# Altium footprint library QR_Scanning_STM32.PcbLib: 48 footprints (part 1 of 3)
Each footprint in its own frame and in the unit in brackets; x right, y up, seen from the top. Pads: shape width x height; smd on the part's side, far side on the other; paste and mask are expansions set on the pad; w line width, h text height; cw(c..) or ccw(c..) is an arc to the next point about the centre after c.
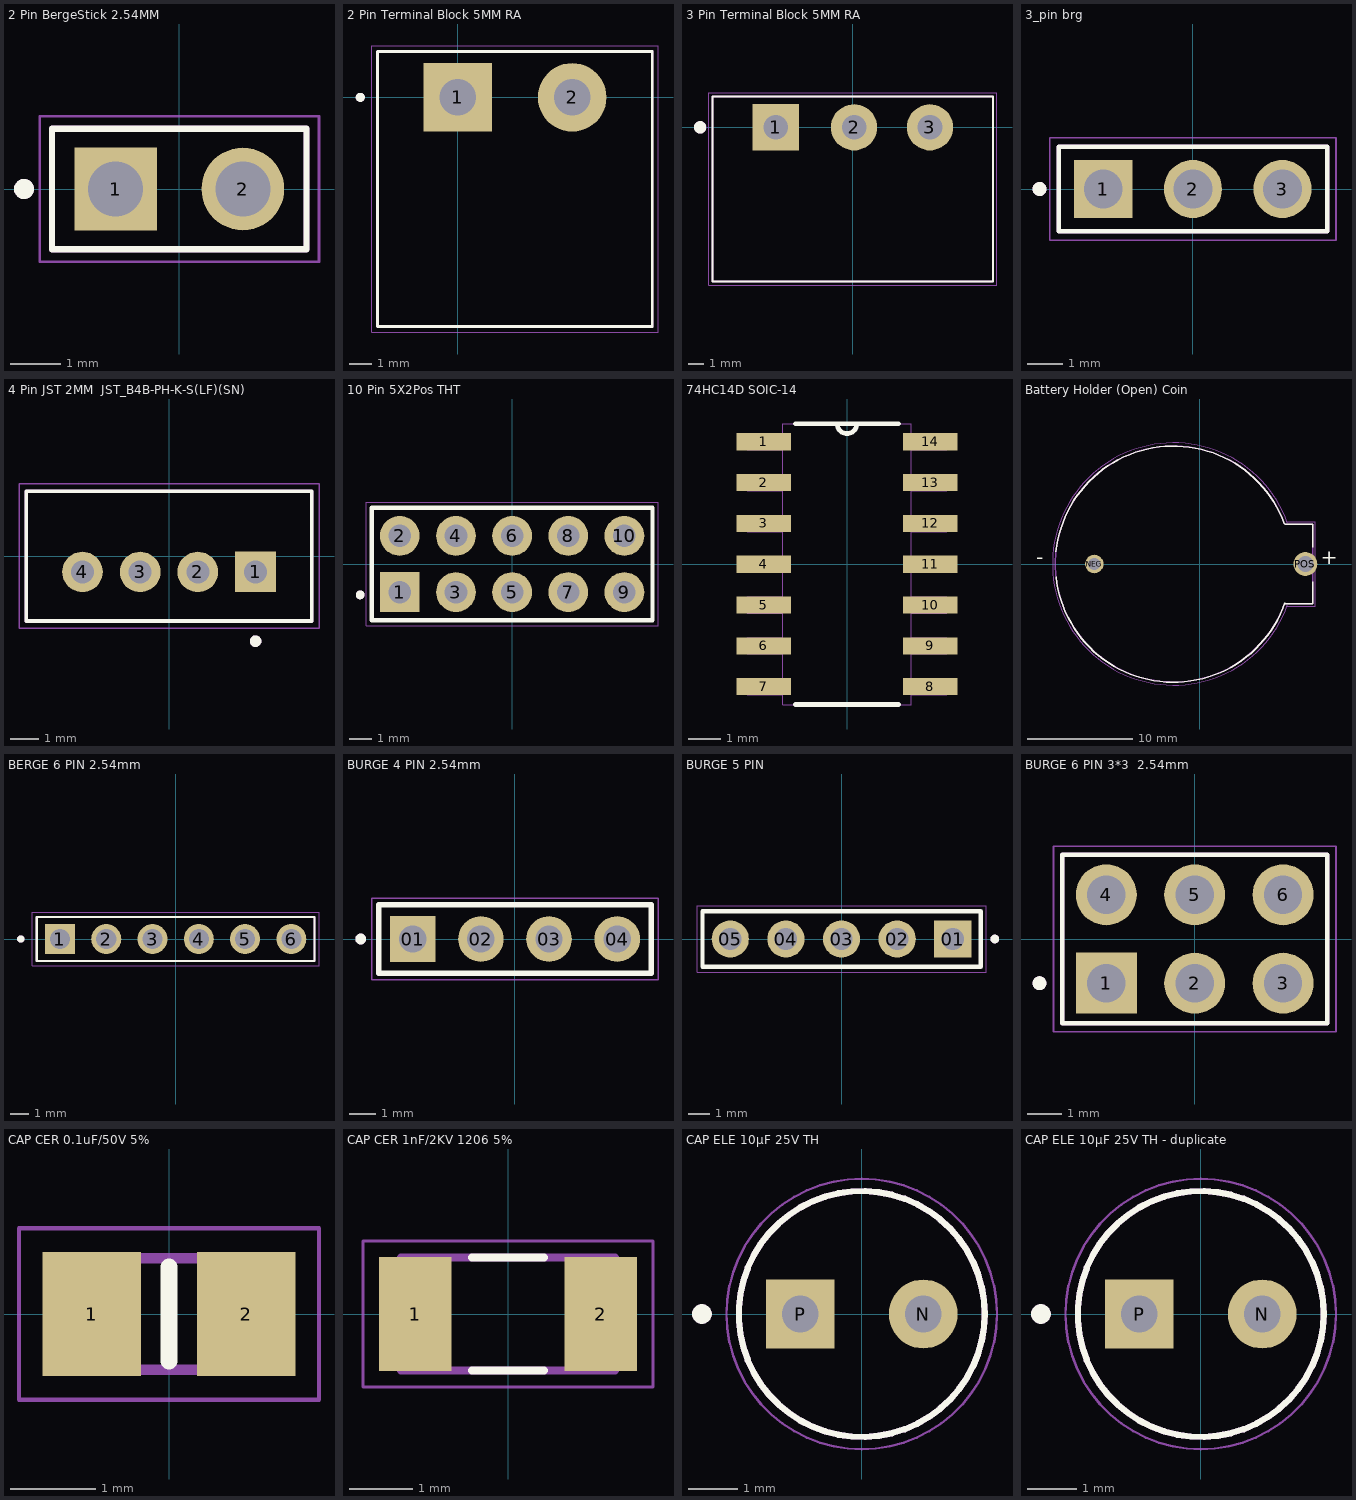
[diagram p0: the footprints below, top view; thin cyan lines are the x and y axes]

## 2 Pin BergeStick 2.54MM [mm] "2 Pin 2Pos THT BergeStick 2.54MM Amphenol 68000-402HLF 3A AMPHENOL_68000-402HLF"
height 10.8
pads (2):
  rect 1.65x1.65 hole 1.1: 1(-1.27,0)
  round 1.65 hole 1.1: 2(1.27,0)
Top Overlay:
  circle w0.2: c-3.1,0 r0.1
  lines w0.127: -2.54,-1.205 2.54,-1.205 2.54,1.205 -2.54,1.205 -2.54,-1.205
Mechanical 13:
  circle w0.2: c-3.1,0 r0.1
  lines w0.127: -2.54,-1.205 2.54,-1.205 2.54,1.205 -2.54,1.205 -2.54,-1.205
Mechanical 15:
  lines w0.05: -2.79,-1.455 2.79,-1.455 2.79,1.455 -2.79,1.455 -2.79,-1.455
3D body "step_temp.STEP": height 8.39, standoff -2.41, extent -2.54,-1.205 2.54,1.205

## 2 Pin Terminal Block 5MM RA [mm] "2 Pin Terminal Block HDR 5MM THT RA_OQ0271510000G"
height 8.5
pads (2):
  rect 3x3 hole 1.6: 1(0,0)
  round 3 hole 1.6: 2(5,0)
Top Overlay:
  circle w0.2: c-4.25,0 r0.1
  lines w0.127: -3.5,-10 -3.5,2 8.5,2 8.5,-10 -3.5,-10
Mechanical 13:
  circle w0.2: c-4.25,0 r0.1
  lines w0.127: -3.5,-10 -3.5,2 8.5,2 8.5,-10 -3.5,-10
Mechanical 15:
  lines w0.05: -3.75,-10.25 -3.75,2.25 8.75,2.25 8.75,-10.25 -3.75,-10.25
3D body "step_temp.STEP": height 8.5, standoff -3.5, extent -3.5,-10 8.5,2

## 3 Pin Terminal Block 5MM RA [mm] "3 Pin Terminal Block HDR 5MM THT RA 231-433_001-000"
pads (3):
  rect 3x3 hole 1.6: 1(-5,0)
  round 3 hole 1.6: 2(0.08,0) 3(5,0)
Top Overlay:
  circle w0.4: c-9.91,0 r0.2
  lines w0.127: -9.1,-10 9.1,-10 9.1,2 -9.1,2 -9.1,-10
Mechanical 13:
  circle w0.4: c-9.906,0 r0.2
  lines w0.127: -9.1,-10 -9.1,2 9.1,2 9.1,-10 -9.1,-10
Mechanical 15:
  lines w0.05: -9.35,-10.25 9.35,-10.25 9.35,2.25 -9.35,2.25 -9.35,-10.25
3D body "2342079-3--3DModel-STEP-1.STEP": height 8.97, standoff -2.28, extent -8.418,-10.064 8.382,1.936

## 3_pin brg [mm] "3_pin brg 2.54mm"
height 8.58
pads (3):
  rect 1.65x1.65 / inner round 1.65 / far side rect 1.65x1.65 hole 1.1: 1(-2.54,0)
  round 1.65 hole 1.1: 2(0,0) 3(2.54,0)
Top Overlay:
  circle w0.2: c-4.35,0 r0.1
  lines w0.127: -3.81,-1.205 -3.81,1.205 3.81,1.205 3.81,-1.205 -3.81,-1.205
Mechanical 13:
  circle w0.2: c-4.35,0 r0.1
  lines w0.127: -3.81,-1.205 -3.81,1.205 3.81,1.205 3.81,-1.205 -3.81,-1.205
Mechanical 15:
  lines w0.05: -4.06,-1.455 -4.06,1.455 4.06,1.455 4.06,-1.455 -4.06,-1.455
3D body "step_temp.STEP": height 8.38, standoff -3.05, extent -3.81,-1.205 3.81,1.205

## 4 Pin JST 2MM  JST_B4B-PH-K-S(LF)(SN) [mm]
pads (4):
  rect 1.408x1.408 hole 0.8: 1(3,-0.55)
  round 1.408 hole 0.8: 2(1,-0.55) 3(-1,-0.55) 4(-3,-0.55)
Top Overlay:
  circle w0.2: c3,-2.95 r0.1
  lines w0.127: -4.95,-2.25 4.95,-2.25 4.95,2.25 -4.95,2.25 -4.95,-2.25
Mechanical 13:
  circle w0.2: c3,-2.95 r0.1
  lines w0.127: -4.95,-2.25 -4.95,2.25 4.95,2.25 4.95,-2.25 -4.95,-2.25
Mechanical 15:
  lines w0.05: -5.2,-2.5 -5.2,2.5 5.2,2.5 5.2,-2.5 -5.2,-2.5
3D body "step_temp.STEP": height 6, standoff -3.4, extent -4.95,-2.25 4.95,2.25

## 10 Pin 5X2Pos THT [mm] "10 Pin 5X2Pos THT BergeStick 2.54MM MTSW-105-X-X-D-X"
pads (10):
  rect 1.8x1.8 hole 1.02: 1(-5.08,-1.27)
  round 1.8 hole 1.02: 2(-5.08,1.27) 3(-2.54,-1.27) 4(-2.54,1.27) 5(0,-1.27) 6(0,1.27) 7(2.54,-1.27) 8(2.54,1.27) 9(5.08,-1.27) 10(5.08,1.27)
Top Overlay:
  circle w0.2: c-6.873,-1.397 r0.1
  lines w0.2: -6.35,-2.54 -6.35,2.54 6.35,2.54 6.35,-2.54 -6.35,-2.54
Mechanical 13:
  circle w0.2: c-6.873,-1.397 r0.1
  lines w0.1: -6.35,-2.54 6.35,-2.54 6.35,2.54 -6.35,2.54 -6.35,-2.54
Mechanical 15:
  lines w0.05: -6.6,-2.79 -6.6,2.79 6.6,2.79 6.6,-2.79 -6.6,-2.79

## 74HC14D SOIC-14 [mil] "Inverter IC 6 Channel Schmitt Trigger 14-SO/SOIC-14"
pads (14):
  rect 67x21 smd: 1(-102,150) 2(-102,100) 3(-102,50) 4(-102,0) 5(-102,-50) 6(-102,-100) 7(-102,-150) 8(102,-150) 9(102,-100) 10(102,-50) 11(102,0) 12(102,50) 13(102,100) 14(102,150)
Top Overlay:
  lines w6: -63,-172 63,-172 ; -63,172 -12,172 ; 63,172 12,172 ; -12,172 ccw(c0,172) 12,172 ; -12,172 12,172
Mechanical 13:
  lines w0: -12,172 ccw(c0,172) 12,172 ; -12,172 12,172 ; -12,172 -79,172 -79,-172 79,-172 79,172 12,172 ; -122,-160 -122,-140 -79,-140 -79,-160 -122,-160 ; -122,-110 -122,-90 -79,-90 -79,-110 -122,-110 ; -122,-60 -122,-40 -79,-40 -79,-60 -122,-60 ; -122,-10 -122,10 -79,10 -79,-10 -122,-10 ; -122,40 -122,60 -79,60 -79,40 -122,40 ; -122,90 -122,110 -79,110 -79,90 -122,90 ; -122,140 -122,160 -79,160 -79,140 -122,140 ; 79,-160 79,-140 122,-140 122,-160 79,-160 ; 79,-110 79,-90 122,-90 122,-110 79,-110 ; 79,-60 79,-40 122,-40 122,-60 79,-60 ; 79,-10 79,10 122,10 122,-10 79,-10 ; 79,40 79,60 122,60 122,40 79,40 ; 79,90 79,110 122,110 122,90 79,90 ; 79,140 79,160 122,160 122,140 79,140
3D body "step_temp.STEP": height 68.9, standoff 0, extent -118.11,-170.28 118.11,170.28

## Battery Holder (Open) Coin [mm] "Battery Holder (Open) Coin"
pads (2):
  round 1.755 hole 1.17: NEG(-10,0)
  round 2.25 hole 1.5: POS(10,0)
Top Overlay:
  lines w0.127: -13.633,1.155 cw(c-2.509,-0.014) 8.002,3.811 ; -13.629,-1.194 ccw(c-2.514,-0.026) 8.054,-3.664 ; 8.024,-3.75 10.699,-3.75 10.7,-1.7 ; 8.024,3.75 10.7,3.75 10.7,1.6
  text "-" at -15.526,0 h1.42
  text "+" at 11.474,0 h1.42
Mechanical 13:
  lines w0.127: 7.997,-3.825 cw(c-2.513,0) 7.997,3.825 ; 8.024,-3.75 10.699,-3.75 10.699,3.75 8.024,3.75
  text "-" at -15.526,0 h1.42
  text "+" at 11.474,0 h1.42
Mechanical 15:
  lines w0.05: 8.274,-4 10.949,-4 10.949,4 8.274,4 ; 8.301,-3.926 cw(c-2.485,0) 8.301,3.926
3D body "BS-7-RED--3DModel-STEP-56544.STEP": height 8.74, standoff -3.35, extent -13.843,-11.303 10.541,11.049

## BERGE 6 PIN 2.54mm [mm] "BERGE 6 PIN 2.54mm, AMPHENOL_68604-406HLF"
height 12.198
pads (6):
  rect 1.65x1.65 / inner round 1.65 / far side rect 1.65x1.65 hole 1.1: 1(-6.35,0)
  round 1.65 hole 1.1: 2(-3.81,0) 3(-1.27,0) 4(1.27,0) 5(3.81,0) 6(6.35,0)
Top Overlay:
  circle w0.2: c-8.5,0 r0.1
  lines w0.127: -7.62,-1.205 -7.62,1.205 7.62,1.205 7.62,-1.205 -7.62,-1.205
Mechanical 13:
  circle w0.2: c-8.5,0 r0.1
  lines w0.127: -7.62,-1.205 -7.62,1.205 7.62,1.205 7.62,-1.205 -7.62,-1.205
Mechanical 15:
  lines w0.05: -7.87,-1.455 7.87,-1.455 7.87,1.455 -7.87,1.455 -7.87,-1.455
3D body "step_temp.STEP": height 12.19, standoff -3.05, extent -7.62,-1.205 7.62,1.205

## BURGE 4 PIN 2.54mm [mm] "BURGE 4 PIN 2.54mm TSW-104-X-X-S-LL"
pads (4):
  rect 1.7x1.7 hole 1.02: 01(-3.81,0)
  round 1.7 hole 1.02: 02(-1.27,0) 03(1.27,0) 04(3.81,0)
Top Overlay:
  circle w0.2: c-5.75,0 r0.1
  lines w0.2: -5.08,-1.27 5.08,-1.27 5.08,1.27 -5.08,1.27 -5.08,-1.27
Mechanical 13:
  circle w0.2: c-5.75,0 r0.1
  lines w0.1: -5.08,-1.27 5.08,-1.27 5.08,1.27 -5.08,1.27 -5.08,-1.27
Mechanical 15:
  lines w0.05: -5.33,-1.52 5.33,-1.52 5.33,1.52 -5.33,1.52 -5.33,-1.52

## BURGE 5 PIN [mm] "MTSW-105-07-T-S-048 BURGE 5 PIN 2.54mm"
pads (5):
  rect 1.7x1.7 hole 1.02: 01(5.08,0)
  round 1.7 hole 1.02: 02(2.54,0) 03(0,0) 04(-2.54,0) 05(-5.08,0)
Top Overlay:
  circle w0.2: c7,0 r0.1
  lines w0.2: -6.35,-1.27 6.35,-1.27 6.35,1.27 -6.35,1.27 -6.35,-1.27
Mechanical 13:
  circle w0.2: c7,0 r0.1
  lines w0.1: -6.35,-1.27 -6.35,1.27 ; -6.35,-1.27 6.35,-1.27 ; -6.35,-1.27 -6.35,1.27 ; -6.35,1.27 6.35,1.27 ; -6.35,1.27 6.35,1.27 ; 6.35,-1.27 6.35,1.27 ; 6.35,-1.27 6.35,1.27
Mechanical 15:
  lines w0.05: -6.6,-1.52 6.6,-1.52 6.6,1.52 -6.6,1.52 -6.6,-1.52

## BURGE 6 PIN 3*3  2.54mm [mm] "BURGE 6 PIN 3*3  2.54mm Positions, Pitch."
pads (6):
  rect 1.75x1.75 hole 1.1: 1(-2.54,-1.27)
  round 1.75 hole 1.1: 2(0,-1.27) 3(2.54,-1.27) 4(-2.54,1.27) 5(0,1.27) 6(2.54,1.27)
Top Overlay:
  circle w0.2: c-4.46,-1.27 r0.1
  lines w0.127: -3.81,-2.415 -3.81,2.415 3.81,2.415 3.81,-2.415 -3.81,-2.415
Mechanical 13:
  circle w0.2: c-4.46,-1.27 r0.1
  lines w0.127: -3.81,-2.415 -3.81,2.415 ; -3.81,-2.415 3.81,-2.415 ; -3.81,-2.415 -3.81,2.415 ; -3.81,2.415 3.81,2.415 ; -3.81,2.415 3.81,2.415 ; 3.81,-2.415 3.81,2.415 ; 3.81,-2.415 3.81,2.415
Mechanical 15:
  lines w0.05: -4.06,-2.665 -4.06,2.665 4.06,2.665 4.06,-2.665 -4.06,-2.665
3D body "step_temp.STEP": height 8.38, standoff -3.05, extent -3.81,-2.415 3.81,2.415

## CAP CER 0.1uF/50V 5% [mm] "CAP CER 0.1uF/50V  Ceramic Capacitor X7R 0805 (2012 Metric) SMT"
pads (2):
  rect 1.15x1.45 smd: 1(-0.9,0) 2(0.9,0)
Top Overlay:
  lines w0.2: 0,-0.55 0,0.55
Mechanical 13:
  region: -0.5,-0.65 -1,-0.65 -1,0.65 -0.5,0.65
  region: 1,-0.65 0.5,-0.65 0.5,0.65 1,0.65
  lines w0.127: -1,-0.65 1,-0.65 1,0.65 -1,0.65 -1,-0.65
Mechanical 15:
  lines w0.05: -1.75,-1 1.75,-1 1.75,1 -1.75,1 -1.75,-1
3D body "step_temp.STEP": height 1.35, standoff 0, extent -1,-0.625 1,0.625

## CAP CER 1nF/2KV 1206 5% [mm] "1000 pF Â±10% 2000V (2kV) Ceramic Capacitor X7R 1206 (3216 Metric) C1206C102KGRACAUTO"
pads (2):
  rect 1.16x1.82 smd: 1(-1.475,0) 2(1.475,0)
Top Overlay:
  lines w0.127: -0.57,-0.9 0.57,-0.9 ; -0.57,0.9 0.57,0.9
Mechanical 13:
  lines w0.127: -1.7,-0.9 -1.7,0.9 1.7,0.9 1.7,-0.9 -1.7,-0.9
Mechanical 15:
  lines w0.05: -2.308,-1.158 -2.308,1.158 2.308,1.158 2.308,-1.158 -2.308,-1.158
3D body "step_temp.STEP": height 1.75, standoff 0, extent -1.6,-0.8 1.6,0.8

## CAP ELE 10µF 25V TH [mm] "10µF 25V Aluminum Electrolytic Capacitors Radial Lead Type THT, Dia-5mm, Pitch-2mm ECEA1EN100UI"
pads (2):
  round 1.4 hole 0.75: N(1.25,0)
  rect 1.4x1.4 hole 0.75: P(-1.25,0)
Top Overlay:
  circle w0.2: c-3.25,0 r0.1
  circle w0.127: c0,0 r2.5
Mechanical 13:
  circle w0.2: c-3.25,0 r0.1
  circle w0.127: c0,0 r2.5
Mechanical 15:
  circle w0.05: c0,0 r2.75
3D body "step_temp.STEP": height 11, standoff -17, extent -2.5,-2.498 2.5,2.498

## CAP ELE 10µF 25V TH - duplicate [mm] "10µF 25V Aluminum Electrolytic Capacitors Radial Lead Type THT, Dia-5mm, Pitch-2mm ECEA1EN100UI"
pads (2):
  round 1.4 hole 0.75: N(1.25,0)
  rect 1.4x1.4 hole 0.75: P(-1.25,0)
Top Overlay:
  circle w0.2: c-3.25,0 r0.1
  circle w0.127: c0,0 r2.5
Mechanical 13:
  circle w0.2: c-3.25,0 r0.1
  circle w0.127: c0,0 r2.5
Mechanical 15:
  circle w0.05: c0,0 r2.75
3D body "step_temp.STEP": height 11, standoff -17, extent -2.5,-2.498 2.5,2.498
